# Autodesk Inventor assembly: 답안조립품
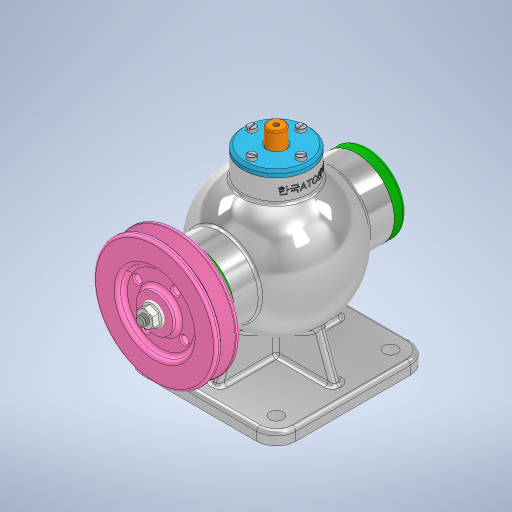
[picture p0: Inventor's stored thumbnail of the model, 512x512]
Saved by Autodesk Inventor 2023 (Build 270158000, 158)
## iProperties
Created: 2023-07
Part Number: 답안조립품
Document SubType Name: Assembly
Designer: Owner
Author: Owner
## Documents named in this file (16)
- C:\Users\Owner\Desktop\730711V1003\답안조립품.iam
- C:\Users\Owner\Desktop\730711V1003\본체.ipt
- C:\Users\Owner\Desktop\730711V1003\뒤커버.ipt
- C:\Users\Owner\Desktop\730711V1003\앞커버.ipt
- C:\Users\Owner\Desktop\730711V1003\상부커버.ipt
- C:\Users\Owner\Desktop\730711V1003\베어링- 6202.ipt
- KS B 2023 - 6202 - 15 x 35 x 11 - 7.8.ipt
- C:\Users\Owner\Desktop\730711V1003\칼라.ipt
- C:\Users\Owner\Desktop\730711V1003\편심축.ipt
- C:\Users\Owner\Desktop\730711V1003\키 4 x 4 x 12.ipt
- C:\Users\Owner\Desktop\730711V1003\오일실 15 30 7.ipt
- C:\Users\Owner\Desktop\730711V1003\V-벨트풀리.ipt
- C:\Users\Owner\Desktop\730711V1003\너트 M8.ipt
- C:\Users\Owner\Desktop\730711V1003\슬라이드.ipt
- C:\Users\Owner\Desktop\730711V1003\볼트 M4 x 12.ipt
- C:\Users\Owner\Desktop\730711V1003\볼트 M4 x 16.ipt
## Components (15 placed, 4 different names)
1. KS B 2023 - 6202 - 15 x 35 x 11 - 7.8:1
2. KS B 2023 - 6202 - 15 x 35 x 11 - 7.8:2
3. V-벨트풀리:1
4. ISO 4762 M4 x 16:2
5. ISO 4762 M4 x 16:6
6. KS B 1021 - 에 따름 ISO 1207 - 미터 A  M 4 x 12:1
7. KS B 1021 - 에 따름 ISO 1207 - 미터 A  M 4 x 12:2
8. KS B 1021 - 에 따름 ISO 1207 - 미터 A  M 4 x 12:3
9. KS B 1021 - 에 따름 ISO 1207 - 미터 A  M 4 x 12:4
10. ISO 4762 M4 x 16:7
11. ISO 4762 M4 x 16:8
12. ISO 4762 M4 x 16:9
13. ISO 4762 M4 x 16:10
14. ISO 4762 M4 x 16:11
15. ISO 4762 M4 x 16:12
